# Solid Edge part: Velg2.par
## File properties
Author: KULL
Template: Iso Metric Part.par
Last saved by: KULL
Revision: 22
Application: Solid Edge
Accuracy: 0,990
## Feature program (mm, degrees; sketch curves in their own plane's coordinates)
pattern "unnamed Pattern 1"
pattern "unnamed Pattern 2"
Other named dimensions: "Pattern_5": XOffset = 45 deg | "Pattern_6": XCount = 8; XOffset = 45 deg
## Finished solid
Body 1: solid body, 389 faces, 931 edges, 512 vertices.
  Faces by surface: blend 256, torus 63, swept 32, cylinder 24, cone 10, plane 2, spun 2
  Edges by curve: intersection 512, circle 403, line 16
Bounding box of the edges (mm; curved faces can reach further): 43.118 x 87.299 x 87.299, from (-41.1766, -43.6493, -43.6493) to (1.9413, 43.6493, 43.6493).
Cylindrical faces by radius (mm): R4 x1, R8 x1, R10 x1, R36.3826 x1, R38.3116 x17, R38.3826 x1, R40.3116 x2
Conical faces (half-angle, radius in mm at the cone's reference point): 14.1898 deg R43.1591 x1, 14.1898 deg R43.6493 x1, 17.3646 deg R36.5649 x1, 17.3646 deg R38.1293 x1, 17.3646 deg R38.5649 x1, 17.3646 deg R40.1293 x1, 75.8102 deg R41.0291 x1, 75.8102 deg R41.5194 x1, 75.8102 deg R43.1591 x1, 75.8102 deg R43.6493 x1
Toroidal faces (ring radius, tube radius in mm): R8.1 r0.1 x1, R13 r3 x1, R34.3116 r4 x17, R36.3116 r4 x2, R36.7771 r0.6 x16, R38.0022 r0.6 x16, R40.3826 r4 x2, R41.9116 r1.6 x2, R41.9116 r3.6 x2, R42.3826 r4 x2, R43.0142 r0.2 x2
Planar faces by outward normal: +x 1, -x 1
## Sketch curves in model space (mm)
line (-10, 0, 10) -> (-7, 0, 10)
line (-10, 0, 0) -> (-10, 0, 10)
line (0, 0, 0) -> (-10, 0, 0)
arc centre (-14.2142, 0, 40.3826) radius 4 from (-14.2142, 0, 36.3826) through (-13.6104, 0, 36.4284) to (-13.0204, 0, 36.5649)
line (-13.0204, 0, 36.5649) -> (-8.0174, 0, 38.1293)
arc centre (-6.8236, 0, 34.3116) radius 4 from (-8.0174, 0, 38.1293) through (-7.4274, 0, 38.2658) to (-6.8236, 0, 38.3116)
line (-6.8236, 0, 38.3116) -> (-2.803, 0, 38.3116)
arc centre (-2.803, 0, 41.9116) radius 3.6 from (-2.803, 0, 38.3116) through (-0.5106, 0, 39.1359) to (0.6871, 0, 41.0291)
line (0.6871, 0, 41.0291) -> (1.2257, 0, 43.1591)
line (-0.7133, 0, 43.6493) -> (1.2257, 0, 43.1591)
line (-1.2519, 0, 41.5194) -> (-0.7133, 0, 43.6493)
arc centre (-2.803, 0, 41.9116) radius 1.6 from (-1.2519, 0, 41.5194) through (-1.8568, 0, 40.6214) to (-2.803, 0, 40.3116)
line (-7.129, 0, 40.3116) -> (-2.803, 0, 40.3116)
arc centre (-7.129, 0, 36.3116) radius 4 from (-8.3228, 0, 40.1293) through (-7.7328, 0, 40.2658) to (-7.129, 0, 40.3116)
line (-13.3258, 0, 38.5649) -> (-8.3228, 0, 40.1293)
arc centre (-14.5196, 0, 42.3826) radius 4 from (-13.3258, 0, 38.5649) through (-13.9158, 0, 38.4284) to (-14.5196, 0, 38.3826)
line (-20, 0, 38.3826) -> (-14.5196, 0, 38.3826)
line (-20, 0, 38.3826) -> (-25.4804, 0, 38.3826)
arc centre (-25.4804, 0, 42.3826) radius 4 from (-26.6742, 0, 38.5649) through (-26.0842, 0, 38.4284) to (-25.4804, 0, 38.3826)
line (-26.6742, 0, 38.5649) -> (-31.6772, 0, 40.1293)
arc centre (-32.871, 0, 36.3116) radius 4 from (-31.6772, 0, 40.1293) through (-32.2672, 0, 40.2658) to (-32.871, 0, 40.3116)
line (-32.871, 0, 40.3116) -> (-37.197, 0, 40.3116)
arc centre (-37.197, 0, 41.9116) radius 1.6 from (-38.7481, 0, 41.5194) through (-38.1432, 0, 40.6214) to (-37.197, 0, 40.3116)
line (-38.7481, 0, 41.5194) -> (-39.2867, 0, 43.6493)
line (-39.2867, 0, 43.6493) -> (-41.2257, 0, 43.1591)
line (-40.6871, 0, 41.0291) -> (-41.2257, 0, 43.1591)
arc centre (-37.197, 0, 41.9116) radius 3.6 from (-37.197, 0, 38.3116) through (-39.4894, 0, 39.1359) to (-40.6871, 0, 41.0291)
line (-33.1764, 0, 38.3116) -> (-37.197, 0, 38.3116)
arc centre (-33.1764, 0, 34.3116) radius 4 from (-31.9826, 0, 38.1293) through (-32.5726, 0, 38.2658) to (-33.1764, 0, 38.3116)
line (-26.9796, 0, 36.5649) -> (-31.9826, 0, 38.1293)
arc centre (-25.7858, 0, 40.3826) radius 4 from (-25.7858, 0, 36.3826) through (-26.3896, 0, 36.4284) to (-26.9796, 0, 36.5649)
line (-20, 0, 36.3826) -> (-25.7858, 0, 36.3826)
line (-20, 0, 36.3826) -> (-14.2142, 0, 36.3826)
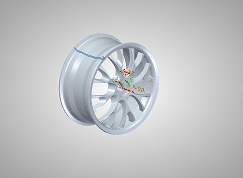
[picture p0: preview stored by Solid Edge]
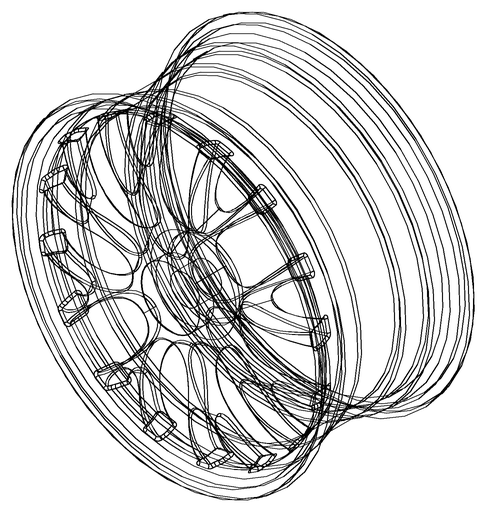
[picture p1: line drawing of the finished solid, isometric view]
